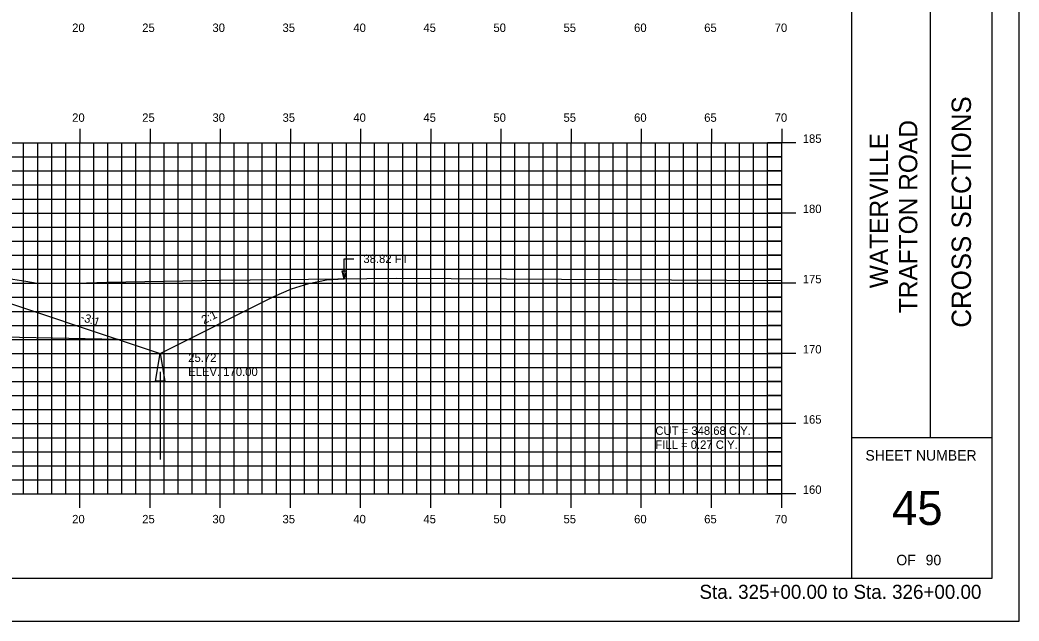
# Model space of a CAD drawing. Extents: x 1140537 to 1140707, y 608981 to 609091.
# Drawn here: x 1140636 to 1140707.2, y 608981.3 to 609024.1 of the extents above; entities that cross this region are included whole.
import ezdxf

# ---------------------------------------------------------------- set-up
doc = ezdxf.new("R2010")
doc.units = 0
for name, color, linetype in [('ANNOTATION', 7, 'Continuous'), ('BORDER', 7, 'Continuous'), ('D_Drainage_Ditch_Line', 7, 'Continuous'), ('D_Roadway_SlopeLines', 7, 'Continuous'), ('D_Roadway_SubGrade', 7, 'Continuous'), ('D_Text_Standard', 7, 'Continuous'), ('H_V ANNOTATION', 7, 'Continuous'), ('HIGHWAY_TITLE', 7, 'Continuous'), ('MAJOR', 7, 'Continuous'), ('MINOR', 7, 'Continuous'), ('PLOT BOUNDARY', 7, 'Continuous'), ('S_Roadway_Centerline', 7, 'Continuous')]:
    doc.layers.add(name, color=color, linetype=linetype)

msp = doc.modelspace()

# ---------------------------------------------------------------- linework, layer by layer
msp.add_lwpolyline([(1140590.652, 609001.047), (1140591.619, 609001.097), (1140592.586, 609000.995), (1140593.553, 609000.74), (1140594.52, 609000.333), (1140597.52, 609001.333), (1140605.244, 609003.907), (1140605.245, 609003.907), (1140609.245, 609004.067), (1140620.245, 609004.287), (1140631.245, 609004.067), (1140635.245, 609003.907), (1140642.968, 609001.333), (1140645.968, 609000.333), (1140654.069, 609004.383), (1140655.319, 609004.932), (1140656.569, 609005.328), (1140657.819, 609005.571), (1140659.069, 609005.661)])
at = {"layer": 'BORDER'}
for p, q in [((1140695.245, 608984.335), (1140695.245, 609089.335)), ((1140700.836, 608994.338), (1140700.836, 609029.338)), ((1140695.245, 608994.338), (1140705.245, 608994.338))]:
    msp.add_line(p, q, dxfattribs=at)
msp.add_lwpolyline([(1140545.245, 608984.335), (1140705.245, 608984.335), (1140705.245, 609089.335), (1140545.245, 609089.335)], close=True, dxfattribs=at)
at = {"layer": 'D_Drainage_Ditch_Line'}
msp.add_line((1140645.968, 608999.021), (1140645.968, 608992.777), dxfattribs=at)
msp.add_lwpolyline([(1140646.296, 608998.364), (1140645.64, 608998.364), (1140645.968, 609000.333)], close=True, dxfattribs=at)
at = {"layer": 'D_Roadway_SlopeLines'}
for points in [[(1140645.968, 609000.333), (1140654.069, 609004.383), (1140655.319, 609004.932), (1140656.569, 609005.328), (1140657.819, 609005.571), (1140659.069, 609005.661)], [(1140642.968, 609001.333), (1140645.968, 609000.333)]]:
    msp.add_lwpolyline(points, dxfattribs=at)
at = {"layer": 'D_Roadway_SubGrade'}
msp.add_lwpolyline([(1140631.245, 609003.651), (1140631.245, 609003.817), (1140635.245, 609003.657), (1140635.245, 609003.907), (1140635.245, 609003.907), (1140642.968, 609001.333), (1140631.245, 609001.567)], close=True, dxfattribs=at)
at = {"layer": 'D_Text_Standard'}
msp.add_lwpolyline([(1140659.069, 609005.633), (1140659.088, 609007.078), (1140659.768, 609007.078)], dxfattribs=at)
msp.add_lwpolyline([(1140659.069, 609005.633), (1140658.931, 609006.217), (1140659.222, 609006.213)], close=True, dxfattribs=at)
at = {"layer": 'MAJOR'}
for p, q in [((1140640.245, 609016.337), (1140640.245, 609015.335)), ((1140645.245, 609016.337), (1140645.245, 609015.335)), ((1140650.245, 609016.337), (1140650.245, 609015.335)), ((1140655.245, 609016.337), (1140655.245, 609015.335)), ((1140660.245, 609016.337), (1140660.245, 609015.335)), ((1140665.245, 609016.337), (1140665.245, 609015.335)), ((1140670.245, 609016.337), (1140670.245, 609015.335)), ((1140675.245, 609016.337), (1140675.245, 609015.335)), ((1140680.245, 609016.337), (1140680.245, 609015.335)), ((1140685.245, 609016.337), (1140685.245, 609015.335)), ((1140690.245, 609016.337), (1140690.245, 609015.335)), ((1140550.245, 609015.335), (1140690.245, 609015.335)), ((1140550.245, 609015.335), (1140690.245, 609015.335)), ((1140640.245, 608990.335), (1140640.245, 609015.335)), ((1140645.245, 608990.335), (1140645.245, 609015.335)), ((1140650.245, 608990.335), (1140650.245, 609015.335)), ((1140655.245, 608990.335), (1140655.245, 609015.335)), ((1140660.245, 608990.335), (1140660.245, 609015.335)), ((1140665.245, 608990.335), (1140665.245, 609015.335)), ((1140670.245, 608990.335), (1140670.245, 609015.335)), ((1140675.245, 608990.335), (1140675.245, 609015.335)), ((1140680.245, 608990.335), (1140680.245, 609015.335)), ((1140685.245, 608990.335), (1140685.245, 609015.335)), ((1140691.247, 609015.335), (1140689.243, 609015.335)), ((1140690.245, 608990.335), (1140690.245, 609015.335)), ((1140690.245, 608990.335), (1140690.245, 609015.335)), ((1140550.245, 609010.335), (1140690.245, 609010.335)), ((1140691.247, 609010.335), (1140689.243, 609010.335)), ((1140550.245, 609005.335), (1140690.245, 609005.335)), ((1140691.247, 609005.335), (1140689.243, 609005.335)), ((1140550.245, 609000.335), (1140690.245, 609000.335)), ((1140691.247, 609000.335), (1140689.243, 609000.335)), ((1140550.245, 608995.335), (1140690.245, 608995.335)), ((1140691.247, 608995.335), (1140689.243, 608995.335)), ((1140550.245, 608990.335), (1140690.245, 608990.335)), ((1140550.245, 608990.335), (1140690.245, 608990.335)), ((1140640.245, 608989.333), (1140640.245, 608990.335)), ((1140645.245, 608989.333), (1140645.245, 608990.335)), ((1140650.245, 608989.333), (1140650.245, 608990.335)), ((1140655.245, 608989.333), (1140655.245, 608990.335)), ((1140660.245, 608989.333), (1140660.245, 608990.335)), ((1140665.245, 608989.333), (1140665.245, 608990.335)), ((1140670.245, 608989.333), (1140670.245, 608990.335)), ((1140675.245, 608989.333), (1140675.245, 608990.335)), ((1140680.245, 608989.333), (1140680.245, 608990.335)), ((1140685.245, 608989.333), (1140685.245, 608990.335)), ((1140691.247, 608990.335), (1140689.243, 608990.335)), ((1140690.245, 608989.333), (1140690.245, 608990.335))]:
    msp.add_line(p, q, dxfattribs=at)
at = {"layer": 'MINOR'}
for p, q in [((1140636.245, 608990.335), (1140636.245, 609015.335)), ((1140637.245, 608990.335), (1140637.245, 609015.335)), ((1140638.245, 608990.335), (1140638.245, 609015.335)), ((1140639.245, 608990.335), (1140639.245, 609015.335)), ((1140641.245, 608990.335), (1140641.245, 609015.335)), ((1140642.245, 608990.335), (1140642.245, 609015.335)), ((1140643.245, 608990.335), (1140643.245, 609015.335)), ((1140644.245, 608990.335), (1140644.245, 609015.335)), ((1140646.245, 608990.335), (1140646.245, 609015.335)), ((1140647.245, 608990.335), (1140647.245, 609015.335)), ((1140648.245, 608990.335), (1140648.245, 609015.335)), ((1140649.245, 608990.335), (1140649.245, 609015.335)), ((1140651.245, 608990.335), (1140651.245, 609015.335)), ((1140652.245, 608990.335), (1140652.245, 609015.335)), ((1140653.245, 608990.335), (1140653.245, 609015.335)), ((1140654.245, 608990.335), (1140654.245, 609015.335)), ((1140656.245, 608990.335), (1140656.245, 609015.335)), ((1140657.245, 608990.335), (1140657.245, 609015.335)), ((1140658.245, 608990.335), (1140658.245, 609015.335)), ((1140659.245, 608990.335), (1140659.245, 609015.335)), ((1140661.245, 608990.335), (1140661.245, 609015.335)), ((1140662.245, 608990.335), (1140662.245, 609015.335)), ((1140663.245, 608990.335), (1140663.245, 609015.335)), ((1140664.245, 608990.335), (1140664.245, 609015.335)), ((1140666.245, 608990.335), (1140666.245, 609015.335)), ((1140667.245, 608990.335), (1140667.245, 609015.335)), ((1140668.245, 608990.335), (1140668.245, 609015.335)), ((1140669.245, 608990.335), (1140669.245, 609015.335)), ((1140671.245, 608990.335), (1140671.245, 609015.335)), ((1140672.245, 608990.335), (1140672.245, 609015.335)), ((1140673.245, 608990.335), (1140673.245, 609015.335)), ((1140674.245, 608990.335), (1140674.245, 609015.335)), ((1140676.245, 608990.335), (1140676.245, 609015.335)), ((1140677.245, 608990.335), (1140677.245, 609015.335)), ((1140678.245, 608990.335), (1140678.245, 609015.335)), ((1140679.245, 608990.335), (1140679.245, 609015.335)), ((1140681.245, 608990.335), (1140681.245, 609015.335)), ((1140682.245, 608990.335), (1140682.245, 609015.335)), ((1140683.245, 608990.335), (1140683.245, 609015.335)), ((1140684.245, 608990.335), (1140684.245, 609015.335)), ((1140686.245, 608990.335), (1140686.245, 609015.335)), ((1140687.245, 608990.335), (1140687.245, 609015.335)), ((1140688.245, 608990.335), (1140688.245, 609015.335)), ((1140689.245, 608990.335), (1140689.245, 609015.335)), ((1140550.245, 609014.335), (1140690.245, 609014.335)), ((1140690.245, 609014.335), (1140689.243, 609014.335)), ((1140550.245, 609013.335), (1140690.245, 609013.335)), ((1140690.245, 609013.335), (1140689.243, 609013.335)), ((1140550.245, 609012.335), (1140690.245, 609012.335)), ((1140690.245, 609012.335), (1140689.243, 609012.335)), ((1140550.245, 609011.335), (1140690.245, 609011.335)), ((1140690.245, 609011.335), (1140689.243, 609011.335)), ((1140550.245, 609009.335), (1140690.245, 609009.335)), ((1140690.245, 609009.335), (1140689.243, 609009.335)), ((1140550.245, 609008.335), (1140690.245, 609008.335)), ((1140690.245, 609008.335), (1140689.243, 609008.335)), ((1140550.245, 609007.335), (1140690.245, 609007.335)), ((1140690.245, 609007.335), (1140689.243, 609007.335)), ((1140550.245, 609006.335), (1140690.245, 609006.335)), ((1140690.245, 609006.335), (1140689.243, 609006.335)), ((1140550.245, 609004.335), (1140690.245, 609004.335)), ((1140690.245, 609004.335), (1140689.243, 609004.335)), ((1140550.245, 609003.335), (1140690.245, 609003.335)), ((1140690.245, 609003.335), (1140689.243, 609003.335)), ((1140550.245, 609002.335), (1140690.245, 609002.335)), ((1140690.245, 609002.335), (1140689.243, 609002.335)), ((1140550.245, 609001.335), (1140690.245, 609001.335)), ((1140690.245, 609001.335), (1140689.243, 609001.335)), ((1140550.245, 608999.335), (1140690.245, 608999.335)), ((1140690.245, 608999.335), (1140689.243, 608999.335)), ((1140550.245, 608998.335), (1140690.245, 608998.335)), ((1140690.245, 608998.335), (1140689.243, 608998.335)), ((1140550.245, 608997.335), (1140690.245, 608997.335)), ((1140690.245, 608997.335), (1140689.243, 608997.335)), ((1140550.245, 608996.335), (1140690.245, 608996.335)), ((1140690.245, 608996.335), (1140689.243, 608996.335)), ((1140550.245, 608994.335), (1140690.245, 608994.335)), ((1140690.245, 608994.335), (1140689.243, 608994.335)), ((1140550.245, 608993.335), (1140690.245, 608993.335)), ((1140690.245, 608993.335), (1140689.243, 608993.335)), ((1140550.245, 608992.335), (1140690.245, 608992.335)), ((1140690.245, 608992.335), (1140689.243, 608992.335)), ((1140550.245, 608991.335), (1140690.245, 608991.335)), ((1140690.245, 608991.335), (1140689.243, 608991.335))]:
    msp.add_line(p, q, dxfattribs=at)
at = {"layer": 'PLOT BOUNDARY'}
msp.add_lwpolyline([(1140537.151, 608981.276), (1140707.151, 608981.276), (1140707.151, 609091.276), (1140537.151, 609091.276)], close=True, dxfattribs=at)
at = {"layer": 'S_Roadway_Centerline'}
msp.add_lwpolyline([(1140633.281, 609005.962), (1140636.4, 609005.487), (1140637.201, 609005.336), (1140640.71, 609005.365), (1140642.174, 609005.424), (1140650.301, 609005.565), (1140662.78, 609005.701), (1140690.245, 609005.534)], dxfattribs=at)

# ---------------------------------------------------------------- texts
at = {"layer": 'ANNOTATION'}
for s, rotation, p in [('-3:1', 341.56521, (1140640.256, 609002.691)), ('2:1', 26.56505, (1140649.091, 609002.412))]:
    msp.add_text(s, height=0.6, rotation=rotation, dxfattribs=at).set_placement(p)
at = {"layer": 'BORDER'}
msp.add_text('CROSS SECTIONS', height=1.37787, rotation=90, dxfattribs=at).set_placement((1140703.729, 609002.172))
for s, height, p in [('SHEET NUMBER', 0.74527, (1140696.21, 608992.701)), ('45', 2.4194, (1140698.106, 608988.118)), ('OF', 0.7453, (1140698.412, 608985.248)), ('90', 0.7453, (1140700.501, 608985.248))]:
    msp.add_text(s, height=height, dxfattribs=at).set_placement(p)
at = {"layer": 'D_Text_Standard'}
for s, p in [('38.82 FT', (1140660.448, 609006.778)), ('25.72', (1140647.968, 608999.733)), ('ELEV. 170.00', (1140647.968, 608998.731)), ('CUT = 348.68 C.Y.', (1140681.245, 608994.535)), ('FILL = 0.27 C.Y.', (1140681.245, 608993.539))]:
    msp.add_text(s, height=0.6, dxfattribs=at).set_placement(p)
at = {"layer": 'H_V ANNOTATION'}
for s, height, p in [('20', 0.6, (1140639.698, 609023.235)), ('25', 0.6, (1140644.69, 609023.235)), ('30', 0.6, (1140649.693, 609023.235)), ('35', 0.6, (1140654.685, 609023.235)), ('40', 0.6, (1140659.731, 609023.235)), ('45', 0.6, (1140664.723, 609023.235)), ('50', 0.6, (1140669.709, 609023.235)), ('55', 0.6, (1140674.701, 609023.235)), ('60', 0.6, (1140679.731, 609023.235)), ('65', 0.6, (1140684.723, 609023.235)), ('70', 0.6, (1140689.747, 609023.235)), ('20', 0.6, (1140639.698, 609016.835)), ('25', 0.6, (1140644.69, 609016.835)), ('30', 0.6, (1140649.693, 609016.835)), ('35', 0.6, (1140654.685, 609016.835)), ('40', 0.6, (1140659.731, 609016.835)), ('45', 0.6, (1140664.723, 609016.835)), ('50', 0.6, (1140669.709, 609016.835)), ('55', 0.6, (1140674.701, 609016.835)), ('60', 0.6, (1140679.731, 609016.835)), ('65', 0.6, (1140684.723, 609016.835)), ('70', 0.6, (1140689.747, 609016.835)), ('185', 0.6, (1140691.745, 609015.335)), ('180', 0.6, (1140691.745, 609010.335)), ('175', 0.6, (1140691.745, 609005.335)), ('170', 0.6, (1140691.745, 609000.335)), ('165', 0.6, (1140691.745, 608995.335)), ('160', 0.6, (1140691.745, 608990.335)), ('20', 0.6, (1140639.698, 608988.235)), ('25', 0.6, (1140644.69, 608988.235)), ('30', 0.6, (1140649.693, 608988.235)), ('35', 0.6, (1140654.685, 608988.235)), ('40', 0.6, (1140659.731, 608988.235)), ('45', 0.6, (1140664.723, 608988.235)), ('50', 0.6, (1140669.709, 608988.235)), ('55', 0.6, (1140674.701, 608988.235)), ('60', 0.6, (1140679.731, 608988.235)), ('65', 0.6, (1140684.723, 608988.235)), ('70', 0.6, (1140689.747, 608988.235)), ('Sta. 325+00.00 to Sta. 326+00.00', 1.0002, (1140684.39, 608982.855))]:
    msp.add_text(s, height=height, dxfattribs=at).set_placement(p)
at = {"layer": 'HIGHWAY_TITLE'}
for s, height, p in [('TRAFTON ROAD', 1.30428, (1140699.904, 609003.201)), ('WATERVILLE', 1.3043, (1140697.817, 609004.98))]:
    msp.add_text(s, height=height, rotation=90, dxfattribs=at).set_placement(p)

doc.saveas('drawing.dxf')
